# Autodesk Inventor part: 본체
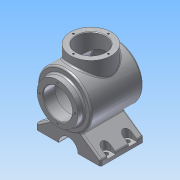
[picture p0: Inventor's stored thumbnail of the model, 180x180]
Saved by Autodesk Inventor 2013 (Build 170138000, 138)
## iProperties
Created: 2017-04
Part Number: 본체
Material: 알루미늄 6061
Document SubType Name: Modeling
Designer: MR
Density: 2.71 g/cm^3
Mass: 1670.75 g
Surface Area: 1066.86 cm^2
Volume: 616.514 cm^3
Author: MR
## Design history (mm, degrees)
sketch "스케치1"
  geometry: L1 (60, -40)-(-60, -40); L2 (-60, -40)-(-60, 40); L3 (-60, 40)-(60, 40); L4 (60, 40)-(60, -40); L5 (60, -40)-(-60, 40); 2 further points
  constraints: 10 end point, 2 parallel, 1 coincident, 1 horizontal, 1 midpoint, 1 perpendicular
  dimensions: "d0" = 120 distance of L2.end L3.end; "d1" = 80 distance of L1.end L2.end
extrude "돌출1" new body sketch "스케치1" distance "d2" = 10; taper "d3" = 0 deg
node "작업 평면1"
sketch "스케치2"
  geometry: L1 (0, 0)-(0, 82); C1 r 50 at (0, 82)
  constraints: 2 end point, 1 centre point, 1 coincident, 1 vertical
  dimensions: "d5" = 82 distance of L1.start L1.end; "d6" = 100 diameter of C1
extrude "돌출2" join sketch "스케치2" distance "d7" = 108; taper "d8" = 0 deg
sketch "스케치3"
  geometry: L1 (10, -40)-(0, -40) reference; L2 (0, -40)-(0, 40) reference; L3 (0, 40)-(10, 40) reference; L4 (10, 40)-(10, -40) reference; L5 (32, -60)-(32, 48) reference; L6 (32, 48)-(132, 48) reference; L7 (132, 48)-(132, -60) reference; L8 (132, -60)-(32, -60) reference; L9 (82, 53)-(82, -60); L10 (82, -60)-(132, -60); L11 (132, -60)-(132, -48.336); A1 r 113 centre (82, 53) between (82, -60) and (132, -48.336); 1 further point
  constraints: 6 end point, 2 collinear, 2 point on circle, 1 centre point, 1 midpoint, 1 perpendicular, 1 point on line, 1 tangent
  dimensions: "d10" = 113 radius of A1
revolve "회전1" sketch "스케치3" stored, may be unused: angle "d12" = 90 deg
sketch "스케치4"
  geometry: L1 (32, -48.336)-(32, 48) reference; L2 (32, 48)-(132, 48) reference; L3 (132, 48)-(132, -48.336) reference; L4 (10, -40)-(0, -40) reference; L5 (0, -40)-(0, 40) reference; L6 (0, 40)-(10, 40) reference; L7 (10, 40)-(10, -40) reference; L8 (82, 53)-(82, -60); L9 (122, 38)-(122, -41.916); L10 (82, 38)-(122, 38); L11 (82, 38)-(82, -50); A1 r 113 centre (82, 53) between (82, -60) and (132, -48.336) reference; A2 r 113 centre (82, 53) between (32, -48.336) and (82, -60) reference; A3 r 103 centre (82, 53) between (82, -50) and (122, -41.916); 1 further point
  constraints: 8 end point, 3 parallel, 2 point on circle, 1 centre point, 1 collinear, 1 point on line
  dimensions: "d13" = 10 radial gap between concentric circles of A2 A3; "d14" = 10 distance between parallel lines of L3 L9; "d15" = 10 distance between parallel lines of L10 L2
revolve "회전2" sketch "스케치4" stored, may be unused: angle "d16" = 90 deg
sketch "스케치5"
  geometry: C1 r 50 at (0, 0) reference; C2 r 38 at (0, 0); 1 further point
  constraints: 1 centre point, 1 coincident
  dimensions: "d21" = 76 diameter of C2
extrude "돌출3" join sketch "스케치5" distance "d22" = 12; taper "d23" = 0 deg
node "작업 평면2"
sketch "스케치7"
  geometry: L1 (120, 0)-(120, 10) reference; L2 (0, 10)-(120, 10) reference; L3 (0, 0)-(0, 10) reference; L4 (0, 10)-(38.416, 36.899); L5 (120, 10)-(81.584, 36.899); A1 r 50 centre (60, 82) between (38.416, 36.899) and (81.584, 36.899) reference; 1 further point
  constraints: 4 end point, 2 point on circle
  dimensions: "d28" = 55 deg angle of L1 L5; "d29" = 55 deg angle of L3 L4
extrude "돌출5" join sketch "스케치7" stored distance "d30" = 12; taper "d31" = 0 deg
sketch "스케치8"
  geometry: C1 r 18 at (60, 0); 1 further point
  constraints: 1 centre point, 1 coincident
  dimensions: "d32" = 36 diameter of C1
extrude "돌출6" cut sketch "스케치8" stored distance "d33" = 12; taper "d34" = 0 deg
sketch "스케치9"
  geometry: C1 r 38 at (0, 0) reference; C2 r 27 at (0, 0); 1 further point
  constraints: 1 centre point, 1 coincident
  dimensions: "d35" = 54 diameter of C2
extrude "돌출7" cut sketch "스케치9" distance "d36" = 22; taper "d37" = 0 deg
sketch "스케치11" dims "d41" = 65
  geometry: L1 (0, 0)-(0, 32.5); C1 r 38 at (0, 0) reference; 2 further points
  constraints: 2 coincident, 2 end point, 1 vertical, 1 vertical alignment, 2 other
hole "구멍1" sketch "스케치11" at (0, 32.5) diameter "d43" = 3.242; stored, may be unused: countersink angle "d47" = 90 deg, drill point angle "d49" = 118 deg; dims "d44" = 8, "d45" = 4, "d46" = 2, "d48" = 10
node "작업 평면3"
sketch "스케치13"
  geometry: L1 (-60, -40)-(-21.584, -40) reference; L2 (-60, 40)-(-60, -40) reference; L3 (-60, -20)-(-21.584, -20); L4 (-50, 40)-(-50, -40); L5 (-50, -28)-(-60, -28); L6 (-50, -12)-(-60, -12); A1 r 8 centre (-50, -20) between (-50, -28) and (-50, -12); 1 further point
  constraints: 8 end point, 6 point on line, 2 parallel, 2 perpendicular, 2 point on circle, 2 tangent, 1 centre point
  dimensions: "d65" = 20 distance between parallel lines of L3 L1; "d66" = 10 distance between parallel lines of L2 L4; "d67" = 16 diameter of A1
extrude "돌출9" cut sketch "스케치13" distance "d68" = 24; taper "d69" = 0 deg
sketch "스케치14"
  geometry: C1 r 4 at (50, 20); A1 r 8 centre (50, 20) between (50, 28) and (50, 12) reference; 1 further point
  constraints: 1 centre point, 1 coincident
  dimensions: "d70" = 8 diameter of C1
extrude "돌출10" cut sketch "스케치14" stored distance "d71" = 24; taper "d72" = 0 deg
fillet "모깎기1" dims "d73" = 3
fillet "모깎기2" dims "d74" = 3
fillet "모깎기3" dims "d75" = 3
fillet "모깎기4" dims "d76" = 3
chamfer "모따기1" distance "d77" = 1; stored, may be unused: second distance "d78" = 2, angle "d79" = 45 deg
node "작업 평면4"
sketch "스케치15"
  geometry: C1 r 50 at (0, 0) reference; 2 further points
  constraints: 1 coincident, 1 other
feature "엠보싱1" sketch "스케치15" dims "d10" = 113, "d80" = 0.5, "d81" = 0
node "작업 평면5"
sketch "스케치16"
  geometry: L1 (-47, 48)-(47, 48) reference; L2 (0, 48)-(0, -2); C1 r 38 at (0, -2); 1 further point
  constraints: 2 end point, 1 centre point, 1 coincident, 1 midpoint, 1 perpendicular
  dimensions: "d84" = 50 distance of L2.start L2.end; "d85" = 76 diameter of C1
extrude "돌출11" join sketch "스케치16" stored distance "d86" = 10; taper "d87" = 0 deg
sketch "스케치17"
  geometry: C1 r 38 at (0, 0) reference; C2 r 27 at (0, 0); 1 further point
  constraints: 1 centre point, 1 coincident
  dimensions: "d88" = 54 diameter of C2
extrude "돌출12" cut sketch "스케치17" distance "d89" = 40; taper "d90" = 0 deg
sketch "스케치18" dims "d91" = 65
  geometry: L1 (0, 0)-(-32.5, 0); C1 r 38 at (0, 0) reference; 2 further points
  constraints: 2 coincident, 2 end point, 1 horizontal, 1 horizontal alignment, 2 other
hole "구멍3" sketch "스케치18" at (-32.5, 0) diameter "d92" = 3.242; stored, may be unused: countersink angle "d96" = 90 deg, drill point angle "d98" = 118 deg; dims "d93" = 8, "d94" = 4, "d95" = 2, "d97" = 10
fillet "모깎기5" dims "d102" = 3
chamfer "모따기2" distance "d103" = 1; stored, may be unused: second distance "d104" = 2, angle "d105" = 45 deg
node "솔리드1"
pattern_circular "원형 패턴1" dims angle "d51" = 360 deg
mirror "대칭1"
mirror "대칭2"
pattern_circular "원형 패턴3" dims angle "d100" = 360 deg
node "절단 모서리 투영1"
node "절단 모서리 투영2"
other parameters: "d4" = 48, "d9" = 226, "d17" = 0.5, "d18" = 2, "d19" = 0, "d24" = 147, "d83" = 147
